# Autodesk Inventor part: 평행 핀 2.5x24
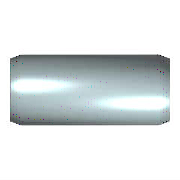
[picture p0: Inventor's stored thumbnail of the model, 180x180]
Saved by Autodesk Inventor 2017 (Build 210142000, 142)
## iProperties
IsCustomPart: 1
Created: 2012-02
Part Number: 평행 핀 2.5x24
Material: 강철, 연강
Description: 평행 핀
Document SubType Name: Modeling
Standard: KS B 1320
Designer: mduedu
Standards Organization: KS
Language: ko-KR
Size Designation: B 2.5 x  24
Categories: <MemberInstance><Categories><Category DisplayName="조임쇠" InternalName="e4da775c-781d-43d5-af7c-5136215cf5a6" Mnemonic="FSTN"><Category DisplayName="핀" InternalNa
Density: 1 g/cm^3
Appearance: 노란색
Author: mduedu
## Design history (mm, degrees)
sketch "스케치"
  geometry: C1 r 1.25 at (0, 0); 1 further point
  constraints: 1 centre point, 1 coincident
  dimensions: "d1" = 2.5 diameter of C1 (= NND)
extrude "본체" new body sketch "스케치" distance "d2" = 24 (= NLG); taper "d3" = 0 deg
chamfer "스케치2" distance "d8" = 0.4 (= PHH); stored, may be unused: angle "d9" = 15 deg (= FAWI), second distance "d12" = 0.4 (= PHH)
node "작업 평면1"
body "Solid1"
chamfer "모따기1" distance "d4" = 0.4 (= PHH); stored, may be unused: angle "d5" = 15 deg (= FAWI), second distance "d11" = 0.4 (= PHH)
other parameters: "NND" = 2.5 [user parameter; used in 1 equation term], "NLG" = 24 [user parameter; used in 1 equation term], "PHH" = 0.4 [user parameter; used in 4 equation terms], "FAWI" = 15 deg [user parameter; used in 2 equation terms], "d13" = 0, "d15" = 0, "d16" = 0, "KAH" = 0.3 [user parameter]
